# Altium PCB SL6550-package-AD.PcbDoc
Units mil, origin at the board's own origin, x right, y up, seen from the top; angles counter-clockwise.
Board outline 6000 x 4000 mil, 2 copper layers (Top Layer, Bottom Layer); 1 components, 0 nets, 64 pads, 0 vias.
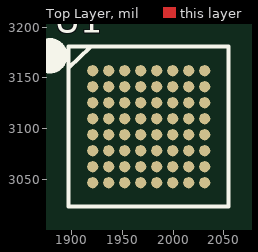
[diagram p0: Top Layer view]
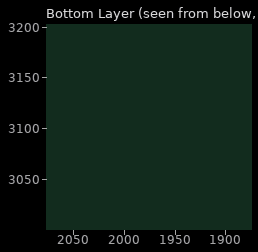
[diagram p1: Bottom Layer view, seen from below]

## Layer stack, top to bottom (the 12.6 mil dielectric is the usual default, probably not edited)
Top Solder: solder mask 0.4, Solder Resist, Dk 3.5
Top Layer: signal copper 1.4
Dielectric 1: dielectric 12.6, FR-4, Dk 4.8
Bottom Layer: signal copper 1.4
Bottom Solder: solder mask 0.4, Solder Resist, Dk 3.5

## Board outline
1000,1000 7000,1000 7000,5000 1000,5000

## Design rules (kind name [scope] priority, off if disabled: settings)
Clearance [All] p1: gap=10
PolygonConnect [All] p1: connectstyle=Relief reliefconductorwidth=10 reliefentries=4 polygonreliefangle="90 Angle" airgapwidth=10
RoutingVias [All] p1: holewidth=28 width=50 viastyle="Through Hole" minholewidth=28 minwidth=50 maxholewidth=28 maxwidth=50
SolderMaskExpansion [All] p1: expansion=4
Width [All] p1: maxlimit=10 minlimit=10 preferedwidth=10
30 further rules are at their usual default settings.

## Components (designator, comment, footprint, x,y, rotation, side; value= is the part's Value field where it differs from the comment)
U1 "SL_6580E" BGA-64-0.4PITCH 1976,3102 r270 top

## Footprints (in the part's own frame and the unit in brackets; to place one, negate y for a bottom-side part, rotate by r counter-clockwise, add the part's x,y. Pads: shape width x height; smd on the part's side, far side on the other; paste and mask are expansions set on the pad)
BGA-64-0.4PITCH [mil]
  round 11 smd: A1(-55.12,-55.12) A2(-55.12,-39.37) A3(-55.12,-23.62) A4(-55.12,-7.87) A5(-55.12,7.87) A6(-55.12,23.62) A7(-55.12,39.37) A8(-55.12,55.12) B1(-39.37,-55.12) B2(-39.37,-39.37) B3(-39.37,-23.62) B4(-39.37,-7.87) B5(-39.37,7.87) B6(-39.37,23.62) B7(-39.37,39.37) B8(-39.37,55.12) C1(-23.62,-55.12) C2(-23.62,-39.37) C3(-23.62,-23.62) C4(-23.62,-7.87) C5(-23.62,7.87) C6(-23.62,23.62) C7(-23.62,39.37) C8(-23.62,55.12) D1(-7.87,-55.12) D2(-7.87,-39.37) D3(-7.87,-23.62) D4(-7.87,-7.87) D5(-7.87,7.87) D6(-7.87,23.62) D7(-7.87,39.37) D8(-7.87,55.12) E1(7.87,-55.12) E2(7.87,-39.37) E3(7.87,-23.62) E4(7.87,-7.87) E5(7.87,7.87) E6(7.87,23.62) E7(7.87,39.37) E8(7.87,55.12) F1(23.62,-55.12) F2(23.62,-39.37) F3(23.62,-23.62) F4(23.62,-7.87) F5(23.62,7.87) F6(23.62,23.62) F7(23.62,39.37) F8(23.62,55.12) G1(39.37,-55.12) G2(39.37,-39.37) G3(39.37,-23.62) G4(39.37,-7.87) G5(39.37,7.87) G6(39.37,23.62) G7(39.37,39.37) G8(39.37,55.12) H1(55.12,-55.12) H2(55.12,-39.37) H3(55.12,-23.62) H4(55.12,-7.87) H5(55.12,7.87) H6(55.12,23.62) H7(55.12,39.37) H8(55.12,55.12)
  silkscreen extent -79,-105 79,79

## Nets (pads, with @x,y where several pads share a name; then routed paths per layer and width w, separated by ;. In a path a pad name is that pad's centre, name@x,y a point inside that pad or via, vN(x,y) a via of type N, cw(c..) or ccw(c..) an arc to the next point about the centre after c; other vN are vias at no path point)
pads on no net: U1.A1 U1.A2 U1.A3 U1.A4 U1.A5 U1.A6 U1.A7 U1.A8 U1.B1 U1.B2 U1.B3 U1.B4 U1.B5 U1.B6 U1.B7 U1.B8 U1.C1 U1.C2 U1.C3 U1.C4 U1.C5 U1.C6 U1.C7 U1.C8 U1.D1 U1.D2 U1.D3 U1.D4 U1.D5 U1.D6 U1.D7 U1.D8 U1.E1 U1.E2 U1.E3 U1.E4 U1.E5 U1.E6 U1.E7 U1.E8 U1.F1 U1.F2 U1.F3 U1.F4 U1.F5 U1.F6 U1.F7 U1.F8 U1.G1 U1.G2 U1.G3 U1.G4 U1.G5 U1.G6 U1.G7 U1.G8 U1.H1 U1.H2 U1.H3 U1.H4 U1.H5 U1.H6 U1.H7 U1.H8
